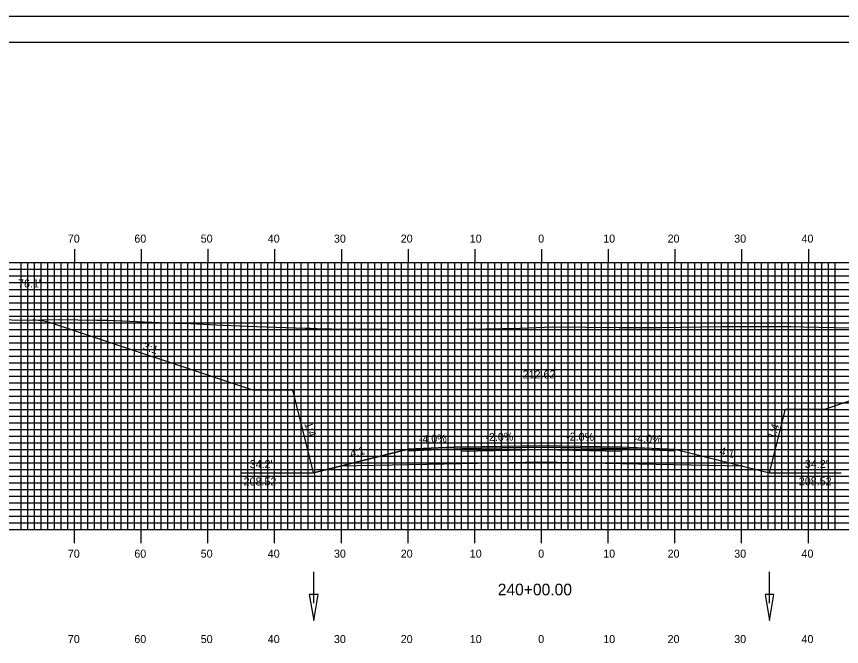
# Model space of a CAD drawing. Extents: x 1801536 to 1801879, y 442591 to 442811.
# Drawn here: x 1801622.9 to 1801746.5, y 442716.2 to 442810.5 of the extents above; entities that cross this region are included whole.
import ezdxf

# ---------------------------------------------------------------- set-up
doc = ezdxf.new("R2010")
doc.units = 0
for name, color, linetype in [('ANNOTATION', 7, 'Continuous'), ('BORDER', 7, 'Continuous'), ('D_Drainage_Ditch_Line', 7, 'Continuous'), ('D_Roadway_Centerline', 7, 'Continuous'), ('D_Roadway_Centerline_Text', 7, 'Continuous'), ('D_Roadway_Edge_Shoulder', 7, 'Continuous'), ('D_Roadway_Edge_TW', 7, 'Continuous'), ('D_Roadway_Pavement', 7, 'Continuous'), ('D_Roadway_SlopeLines', 7, 'Continuous'), ('D_Roadway_SubGrade', 7, 'Continuous'), ('D_Text_Standard', 7, 'Continuous'), ('H_V ANNOTATION', 7, 'Continuous'), ('M_Roadway_Centerline', 7, 'Continuous'), ('M_Utilities_Pole', 7, 'Continuous'), ('MAJOR', 7, 'Continuous'), ('MINOR', 7, 'Continuous'), ('PDRAIN', 7, 'Continuous'), ('PLOT BOUNDARY', 7, 'Continuous'), ('S_Roadway_Centerline', 7, 'Continuous')]:
    doc.layers.add(name, color=color, linetype=linetype)

msp = doc.modelspace()

# ---------------------------------------------------------------- linework, layer by layer
at = {"layer": 'ANNOTATION'}
for p, q in [((1801735.75, 442742.19), (1801738.14, 442751.74)), ((1801738.14, 442751.74), (1801744.14, 442751.74))]:
    msp.add_line(p, q, dxfattribs=at)
at = {"layer": 'BORDER'}
msp.add_lwpolyline([(1801551.98, 442596.67), (1801871.98, 442596.67), (1801871.98, 442806.67), (1801551.98, 442806.67)], close=True, dxfattribs=at)
at = {"layer": 'D_Drainage_Ditch_Line'}
for p, q in [((1801667.43, 442722.65), (1801667.43, 442727.35)), ((1801735.78, 442722.65), (1801735.78, 442727.35))]:
    msp.add_line(p, q, dxfattribs=at)
for points in [[(1801668.09, 442723.96), (1801666.77, 442723.96), (1801667.43, 442720.03)], [(1801736.43, 442723.96), (1801735.12, 442723.96), (1801735.78, 442720.03)]]:
    msp.add_lwpolyline(points, close=True, dxfattribs=at)
at = {"layer": 'D_Roadway_Centerline'}
msp.add_lwpolyline([(1801667.4, 442742.19), (1801671.4, 442743.19), (1801681.58, 442745.73), (1801689.58, 442746.05), (1801701.58, 442746.29), (1801713.58, 442746.05), (1801721.58, 442745.73), (1801731.75, 442743.19), (1801735.75, 442742.19)], dxfattribs=at)
at = {"layer": 'D_Roadway_Edge_Shoulder'}
for points in [[(1801689.58, 442746.05), (1801681.58, 442745.73), (1801681.58, 442745.48), (1801689.58, 442745.8)], [(1801713.58, 442746.05), (1801721.58, 442745.73), (1801721.58, 442745.48), (1801713.58, 442745.8)]]:
    msp.add_lwpolyline(points, close=True, dxfattribs=at)
at = {"layer": 'D_Roadway_Edge_TW'}
msp.add_lwpolyline([(1801689.58, 442745.8), (1801689.58, 442746.05), (1801701.58, 442746.29), (1801713.58, 442746.05), (1801713.58, 442745.8), (1801701.58, 442746.04)], close=True, dxfattribs=at)
at = {"layer": 'D_Roadway_Pavement'}
msp.add_lwpolyline([(1801689.58, 442745.38), (1801689.58, 442745.8), (1801701.58, 442746.04), (1801713.58, 442745.8), (1801713.58, 442745.38), (1801701.58, 442745.62)], close=True, dxfattribs=at)
at = {"layer": 'D_Roadway_SlopeLines'}
for p, q in [((1801776.98, 442762.69), (1801744.14, 442751.74)), ((1801667.4, 442742.19), (1801664.84, 442752.41))]:
    msp.add_line(p, q, dxfattribs=at)
for points in [[(1801664.84, 442752.41), (1801664.31, 442754.57), (1801658.31, 442754.57), (1801628.6, 442764.47)], [(1801681.58, 442745.73), (1801667.4, 442742.19)], [(1801721.58, 442745.73), (1801735.75, 442742.19)]]:
    msp.add_lwpolyline(points, dxfattribs=at)
msp.add_arc((1801624.84, 442753.19), 11.89, 71.5651, 87.7423, dxfattribs=at)
at = {"layer": 'D_Roadway_SubGrade'}
msp.add_lwpolyline([(1801689.58, 442743.55), (1801671.4, 442743.19), (1801681.58, 442745.73), (1801681.58, 442745.48), (1801689.58, 442745.8), (1801701.58, 442746.04), (1801713.58, 442745.8), (1801721.58, 442745.48), (1801721.58, 442745.73), (1801731.75, 442743.19), (1801713.58, 442743.55), (1801701.58, 442743.79)], close=True, dxfattribs=at)
at = {"layer": 'M_Utilities_Pole'}
msp.add_line((1801639.43, 442764.15), (1801639.43, 442764.14), dxfattribs=at)
msp.add_circle((1801639.43, 442764.14), 0.00417, dxfattribs=at)
at = {"layer": 'MAJOR'}
for p, q in [((1801631.58, 442775.67), (1801631.58, 442773.67)), ((1801641.58, 442775.67), (1801641.58, 442773.67)), ((1801651.58, 442775.67), (1801651.58, 442773.67)), ((1801661.58, 442775.67), (1801661.58, 442773.67)), ((1801671.58, 442775.67), (1801671.58, 442773.67)), ((1801681.58, 442775.67), (1801681.58, 442773.67)), ((1801691.58, 442775.67), (1801691.58, 442773.67)), ((1801701.58, 442775.67), (1801701.58, 442773.67)), ((1801711.58, 442775.67), (1801711.58, 442773.67)), ((1801721.58, 442775.67), (1801721.58, 442773.67)), ((1801731.58, 442775.67), (1801731.58, 442773.67)), ((1801741.58, 442775.67), (1801741.58, 442773.67)), ((1801561.58, 442773.67), (1801841.58, 442773.67)), ((1801561.58, 442773.67), (1801841.58, 442773.67)), ((1801631.58, 442733.67), (1801631.58, 442773.67)), ((1801641.58, 442733.67), (1801641.58, 442773.67)), ((1801651.58, 442733.67), (1801651.58, 442773.67)), ((1801661.58, 442733.67), (1801661.58, 442773.67)), ((1801671.58, 442733.67), (1801671.58, 442773.67)), ((1801681.58, 442733.67), (1801681.58, 442773.67)), ((1801691.58, 442733.67), (1801691.58, 442773.67)), ((1801701.58, 442733.67), (1801701.58, 442773.67)), ((1801711.58, 442733.67), (1801711.58, 442773.67)), ((1801721.58, 442733.67), (1801721.58, 442773.67)), ((1801731.58, 442733.67), (1801731.58, 442773.67)), ((1801741.58, 442733.67), (1801741.58, 442773.67)), ((1801561.58, 442768.67), (1801841.58, 442768.67)), ((1801561.58, 442763.67), (1801841.58, 442763.67)), ((1801561.58, 442758.67), (1801841.58, 442758.67)), ((1801561.58, 442753.67), (1801841.58, 442753.67)), ((1801561.58, 442748.67), (1801841.58, 442748.67)), ((1801561.58, 442743.67), (1801841.58, 442743.67)), ((1801561.58, 442738.67), (1801841.58, 442738.67)), ((1801561.58, 442733.67), (1801841.58, 442733.67)), ((1801561.58, 442733.67), (1801841.58, 442733.67)), ((1801631.58, 442731.66), (1801631.58, 442733.67)), ((1801641.58, 442731.66), (1801641.58, 442733.67)), ((1801651.58, 442731.66), (1801651.58, 442733.67)), ((1801661.58, 442731.66), (1801661.58, 442733.67)), ((1801671.58, 442731.66), (1801671.58, 442733.67)), ((1801681.58, 442731.66), (1801681.58, 442733.67)), ((1801691.58, 442731.66), (1801691.58, 442733.67)), ((1801701.58, 442731.66), (1801701.58, 442733.67)), ((1801711.58, 442731.66), (1801711.58, 442733.67)), ((1801721.58, 442731.66), (1801721.58, 442733.67)), ((1801731.58, 442731.66), (1801731.58, 442733.67)), ((1801741.58, 442731.66), (1801741.58, 442733.67))]:
    msp.add_line(p, q, dxfattribs=at)
at = {"layer": 'MINOR'}
for p, q in [((1801561.58, 442772.67), (1801841.58, 442772.67)), ((1801623.58, 442733.67), (1801623.58, 442773.67)), ((1801624.58, 442733.67), (1801624.58, 442773.67)), ((1801625.58, 442733.67), (1801625.58, 442773.67)), ((1801626.58, 442733.67), (1801626.58, 442773.67)), ((1801627.58, 442733.67), (1801627.58, 442773.67)), ((1801628.58, 442733.67), (1801628.58, 442773.67)), ((1801629.58, 442733.67), (1801629.58, 442773.67)), ((1801630.58, 442733.67), (1801630.58, 442773.67)), ((1801632.58, 442733.67), (1801632.58, 442773.67)), ((1801633.58, 442733.67), (1801633.58, 442773.67)), ((1801634.58, 442733.67), (1801634.58, 442773.67)), ((1801635.58, 442733.67), (1801635.58, 442773.67)), ((1801636.58, 442733.67), (1801636.58, 442773.67)), ((1801637.58, 442733.67), (1801637.58, 442773.67)), ((1801638.58, 442733.67), (1801638.58, 442773.67)), ((1801639.58, 442733.67), (1801639.58, 442773.67)), ((1801640.58, 442733.67), (1801640.58, 442773.67)), ((1801642.58, 442733.67), (1801642.58, 442773.67)), ((1801643.58, 442733.67), (1801643.58, 442773.67)), ((1801644.58, 442733.67), (1801644.58, 442773.67)), ((1801645.58, 442733.67), (1801645.58, 442773.67)), ((1801646.58, 442733.67), (1801646.58, 442773.67)), ((1801647.58, 442733.67), (1801647.58, 442773.67)), ((1801648.58, 442733.67), (1801648.58, 442773.67)), ((1801649.58, 442733.67), (1801649.58, 442773.67)), ((1801650.58, 442733.67), (1801650.58, 442773.67)), ((1801652.58, 442733.67), (1801652.58, 442773.67)), ((1801653.58, 442733.67), (1801653.58, 442773.67)), ((1801654.58, 442733.67), (1801654.58, 442773.67)), ((1801655.58, 442733.67), (1801655.58, 442773.67)), ((1801656.58, 442733.67), (1801656.58, 442773.67)), ((1801657.58, 442733.67), (1801657.58, 442773.67)), ((1801658.58, 442733.67), (1801658.58, 442773.67)), ((1801659.58, 442733.67), (1801659.58, 442773.67)), ((1801660.58, 442733.67), (1801660.58, 442773.67)), ((1801662.58, 442733.67), (1801662.58, 442773.67)), ((1801663.58, 442733.67), (1801663.58, 442773.67)), ((1801664.58, 442733.67), (1801664.58, 442773.67)), ((1801665.58, 442733.67), (1801665.58, 442773.67)), ((1801666.58, 442733.67), (1801666.58, 442773.67)), ((1801667.58, 442733.67), (1801667.58, 442773.67)), ((1801668.58, 442733.67), (1801668.58, 442773.67)), ((1801669.58, 442733.67), (1801669.58, 442773.67)), ((1801670.58, 442733.67), (1801670.58, 442773.67)), ((1801672.58, 442733.67), (1801672.58, 442773.67)), ((1801673.58, 442733.67), (1801673.58, 442773.67)), ((1801674.58, 442733.67), (1801674.58, 442773.67)), ((1801675.58, 442733.67), (1801675.58, 442773.67)), ((1801676.58, 442733.67), (1801676.58, 442773.67)), ((1801677.58, 442733.67), (1801677.58, 442773.67)), ((1801678.58, 442733.67), (1801678.58, 442773.67)), ((1801679.58, 442733.67), (1801679.58, 442773.67)), ((1801680.58, 442733.67), (1801680.58, 442773.67)), ((1801682.58, 442733.67), (1801682.58, 442773.67)), ((1801683.58, 442733.67), (1801683.58, 442773.67)), ((1801684.58, 442733.67), (1801684.58, 442773.67)), ((1801685.58, 442733.67), (1801685.58, 442773.67)), ((1801686.58, 442733.67), (1801686.58, 442773.67)), ((1801687.58, 442733.67), (1801687.58, 442773.67)), ((1801688.58, 442733.67), (1801688.58, 442773.67)), ((1801689.58, 442733.67), (1801689.58, 442773.67)), ((1801690.58, 442733.67), (1801690.58, 442773.67)), ((1801692.58, 442733.67), (1801692.58, 442773.67)), ((1801693.58, 442733.67), (1801693.58, 442773.67)), ((1801694.58, 442733.67), (1801694.58, 442773.67)), ((1801695.58, 442733.67), (1801695.58, 442773.67)), ((1801696.58, 442733.67), (1801696.58, 442773.67)), ((1801697.58, 442733.67), (1801697.58, 442773.67)), ((1801698.58, 442733.67), (1801698.58, 442773.67)), ((1801699.58, 442733.67), (1801699.58, 442773.67)), ((1801700.58, 442733.67), (1801700.58, 442773.67)), ((1801702.58, 442733.67), (1801702.58, 442773.67)), ((1801703.58, 442733.67), (1801703.58, 442773.67)), ((1801704.58, 442733.67), (1801704.58, 442773.67)), ((1801705.58, 442733.67), (1801705.58, 442773.67)), ((1801706.58, 442733.67), (1801706.58, 442773.67)), ((1801707.58, 442733.67), (1801707.58, 442773.67)), ((1801708.58, 442733.67), (1801708.58, 442773.67)), ((1801709.58, 442733.67), (1801709.58, 442773.67)), ((1801710.58, 442733.67), (1801710.58, 442773.67)), ((1801712.58, 442733.67), (1801712.58, 442773.67)), ((1801713.58, 442733.67), (1801713.58, 442773.67)), ((1801714.58, 442733.67), (1801714.58, 442773.67)), ((1801715.58, 442733.67), (1801715.58, 442773.67)), ((1801716.58, 442733.67), (1801716.58, 442773.67)), ((1801717.58, 442733.67), (1801717.58, 442773.67)), ((1801718.58, 442733.67), (1801718.58, 442773.67)), ((1801719.58, 442733.67), (1801719.58, 442773.67)), ((1801720.58, 442733.67), (1801720.58, 442773.67)), ((1801722.58, 442733.67), (1801722.58, 442773.67)), ((1801723.58, 442733.67), (1801723.58, 442773.67)), ((1801724.58, 442733.67), (1801724.58, 442773.67)), ((1801725.58, 442733.67), (1801725.58, 442773.67)), ((1801726.58, 442733.67), (1801726.58, 442773.67)), ((1801727.58, 442733.67), (1801727.58, 442773.67)), ((1801728.58, 442733.67), (1801728.58, 442773.67)), ((1801729.58, 442733.67), (1801729.58, 442773.67)), ((1801730.58, 442733.67), (1801730.58, 442773.67)), ((1801732.58, 442733.67), (1801732.58, 442773.67)), ((1801733.58, 442733.67), (1801733.58, 442773.67)), ((1801734.58, 442733.67), (1801734.58, 442773.67)), ((1801735.58, 442733.67), (1801735.58, 442773.67)), ((1801736.58, 442733.67), (1801736.58, 442773.67)), ((1801737.58, 442733.67), (1801737.58, 442773.67)), ((1801738.58, 442733.67), (1801738.58, 442773.67)), ((1801739.58, 442733.67), (1801739.58, 442773.67)), ((1801740.58, 442733.67), (1801740.58, 442773.67)), ((1801742.58, 442733.67), (1801742.58, 442773.67)), ((1801743.58, 442733.67), (1801743.58, 442773.67)), ((1801744.58, 442733.67), (1801744.58, 442773.67)), ((1801745.58, 442733.67), (1801745.58, 442773.67)), ((1801561.58, 442771.67), (1801841.58, 442771.67)), ((1801561.58, 442770.67), (1801841.58, 442770.67)), ((1801561.58, 442769.67), (1801841.58, 442769.67)), ((1801561.58, 442767.67), (1801841.58, 442767.67)), ((1801561.58, 442766.67), (1801841.58, 442766.67)), ((1801561.58, 442765.67), (1801841.58, 442765.67)), ((1801561.58, 442764.67), (1801841.58, 442764.67)), ((1801561.58, 442762.67), (1801841.58, 442762.67)), ((1801561.58, 442761.67), (1801841.58, 442761.67)), ((1801561.58, 442760.67), (1801841.58, 442760.67)), ((1801561.58, 442759.67), (1801841.58, 442759.67)), ((1801561.58, 442757.67), (1801841.58, 442757.67)), ((1801561.58, 442756.67), (1801841.58, 442756.67)), ((1801561.58, 442755.67), (1801841.58, 442755.67)), ((1801561.58, 442754.67), (1801841.58, 442754.67)), ((1801561.58, 442752.67), (1801841.58, 442752.67)), ((1801561.58, 442751.67), (1801841.58, 442751.67)), ((1801561.58, 442750.67), (1801841.58, 442750.67)), ((1801561.58, 442749.67), (1801841.58, 442749.67)), ((1801561.58, 442747.67), (1801841.58, 442747.67)), ((1801561.58, 442746.67), (1801841.58, 442746.67)), ((1801561.58, 442745.67), (1801841.58, 442745.67)), ((1801561.58, 442744.67), (1801841.58, 442744.67)), ((1801561.58, 442742.67), (1801841.58, 442742.67)), ((1801561.58, 442741.67), (1801841.58, 442741.67)), ((1801561.58, 442740.67), (1801841.58, 442740.67)), ((1801561.58, 442739.67), (1801841.58, 442739.67)), ((1801561.58, 442737.67), (1801841.58, 442737.67)), ((1801561.58, 442736.67), (1801841.58, 442736.67)), ((1801561.58, 442735.67), (1801841.58, 442735.67)), ((1801561.58, 442734.67), (1801841.58, 442734.67))]:
    msp.add_line(p, q, dxfattribs=at)
at = {"layer": 'PDRAIN'}
for p, q in [((1801656.68, 442742.19), (1801667.4, 442742.19)), ((1801735.75, 442742.19), (1801746.52, 442742.19))]:
    msp.add_line(p, q, dxfattribs=at)
at = {"layer": 'PLOT BOUNDARY'}
msp.add_lwpolyline([(1801535.79, 442590.55), (1801875.79, 442590.55), (1801875.79, 442810.55), (1801535.79, 442810.55)], close=True, dxfattribs=at)
at = {"layer": 'S_Roadway_Centerline'}
msp.add_lwpolyline([(1801617.23, 442765.23), (1801623.76, 442765.04), (1801629.23, 442765.13), (1801634.94, 442765.07), (1801636.6, 442765.05), (1801646.45, 442764.62), (1801647.98, 442764.6), (1801653.79, 442764.29), (1801658.92, 442764.1), (1801666.17, 442763.86), (1801666.96, 442763.86), (1801668.88, 442763.76), (1801670.12, 442763.73), (1801687.36, 442763.66), (1801693.24, 442763.75), (1801698.33, 442763.83), (1801703.27, 442764.05), (1801713.22, 442763.94), (1801719.39, 442763.93), (1801728.44, 442764.08), (1801738.99, 442764.09), (1801740.84, 442764.07), (1801750.1, 442763.83)], dxfattribs=at)

# ---------------------------------------------------------------- texts
at = {"layer": 'ANNOTATION'}
for s, rotation, p in [('3:1', 341.5651, (1801641.74, 442760.65)), ('3:1', 341.5651, (1801641.74, 442760.65)), ('1:4', 289.484, (1801666.01, 442749.53)), ('1:4', 70.516, (1801736.52, 442747.16)), ('-4.0%', 2.2906, (1801683.21, 442746.6)), ('-2.0%', 1.1458, (1801693.18, 442746.92)), ('-2.0%', 358.8542, (1801705.26, 442747.02)), ('-4.0%', 357.7094, (1801715.37, 442746.78)), ('4:1', 14.0362, (1801673.02, 442744.45)), ('4:1', 345.9638, (1801728.17, 442744.94))]:
    msp.add_text(s, height=1.2, rotation=rotation, dxfattribs=at).set_placement(p)
for s, p in [("34.2'", (1801741.06, 442742.91)), ("34.2'", (1801657.84, 442742.88)), ('208.52', (1801656.93, 442740.28)), ('208.52', (1801740.15, 442740.31))]:
    msp.add_text(s, height=1.2, dxfattribs=at).set_placement(p)
at = {"layer": 'D_Roadway_Centerline'}
for s, p in [('C', (1801701.57, 442746.29)), ('L', (1801701.58, 442746.28))]:
    msp.add_text(s, height=0.0146, dxfattribs=at).set_placement(p)
at = {"layer": 'D_Roadway_Centerline_Text'}
msp.add_text('212.62', height=1.2, dxfattribs=at).set_placement((1801698.76, 442756.32))
at = {"layer": 'D_Text_Standard'}
msp.add_text("76.1'", height=1.2, dxfattribs=at).set_placement((1801623.11, 442769.95))
at = {"layer": 'H_V ANNOTATION'}
for s, height, p in [('70', 1.2, (1801630.58, 442776.67)), ('60', 1.2, (1801640.55, 442776.67)), ('50', 1.2, (1801650.5, 442776.67)), ('40', 1.2, (1801660.55, 442776.67)), ('30', 1.2, (1801670.47, 442776.67)), ('20', 1.2, (1801680.48, 442776.67)), ('10', 1.2, (1801690.83, 442776.67)), ('0', 1.2, (1801701.09, 442776.67)), ('10', 1.2, (1801710.83, 442776.67)), ('20', 1.2, (1801720.48, 442776.67)), ('30', 1.2, (1801730.47, 442776.67)), ('40', 1.2, (1801740.55, 442776.67)), ('70', 1.2, (1801630.58, 442729.47)), ('60', 1.2, (1801640.55, 442729.47)), ('50', 1.2, (1801650.5, 442729.47)), ('40', 1.2, (1801660.55, 442729.47)), ('30', 1.2, (1801670.47, 442729.47)), ('20', 1.2, (1801680.48, 442729.47)), ('10', 1.2, (1801690.83, 442729.47)), ('0', 1.2, (1801701.09, 442729.47)), ('10', 1.2, (1801710.83, 442729.47)), ('20', 1.2, (1801720.48, 442729.47)), ('30', 1.2, (1801730.47, 442729.47)), ('40', 1.2, (1801740.55, 442729.47)), ('240+00.00', 1.75, (1801695.02, 442723.82)), ('70', 1.2, (1801630.58, 442716.67)), ('60', 1.2, (1801640.55, 442716.67)), ('50', 1.2, (1801650.5, 442716.67)), ('40', 1.2, (1801660.55, 442716.67)), ('30', 1.2, (1801670.47, 442716.67)), ('20', 1.2, (1801680.48, 442716.67)), ('10', 1.2, (1801690.83, 442716.67)), ('0', 1.2, (1801701.09, 442716.67)), ('10', 1.2, (1801710.83, 442716.67)), ('20', 1.2, (1801720.48, 442716.67)), ('30', 1.2, (1801730.47, 442716.67)), ('40', 1.2, (1801740.55, 442716.67))]:
    msp.add_text(s, height=height, dxfattribs=at).set_placement(p)
at = {"layer": 'M_Roadway_Centerline'}
for s, p in [('C', (1801629.22, 442765.13)), ('L', (1801629.23, 442765.12))]:
    msp.add_text(s, height=0.0146, dxfattribs=at).set_placement(p)

doc.saveas('drawing.dxf')
